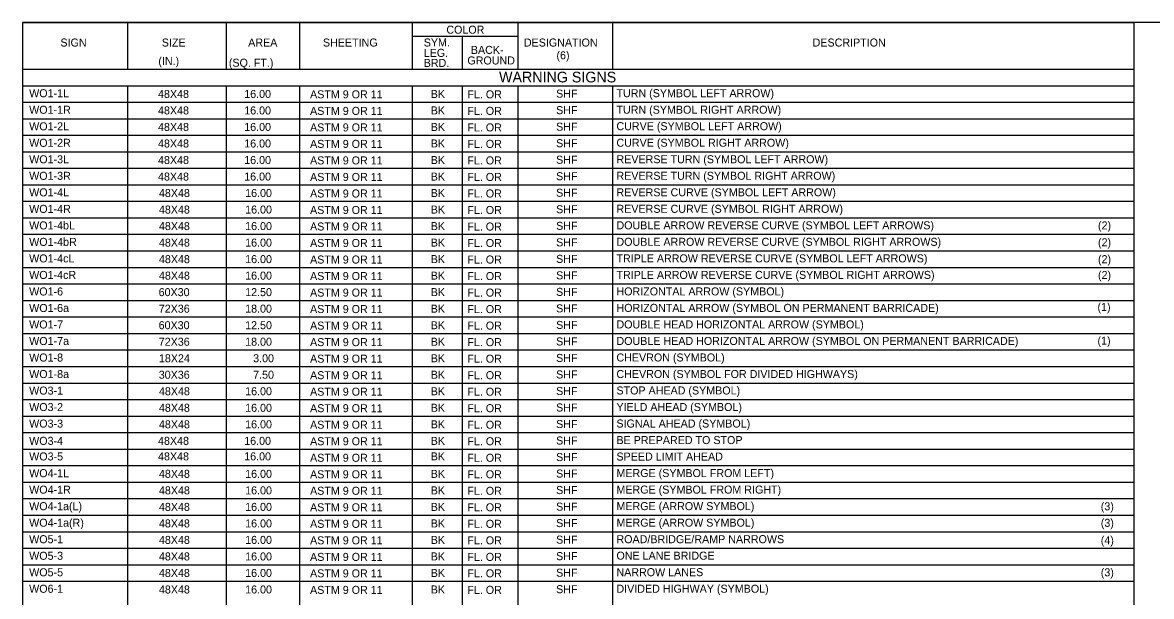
# Model space of a CAD drawing. Extents: x -439.1 to -407.9, y -458.1 to -437.7.
# Drawn here: x -439.11 to -418.9, y -447.95 to -437.68 of the extents above; entities that cross this region are included whole.
import ezdxf

# ---------------------------------------------------------------- set-up
doc = ezdxf.new("R2010")
doc.units = 0
for name, color, linetype in [('Draft_Named_Boundary', 7, 'Continuous'), ('Level 4', 7, 'Continuous'), ('Level 45', 7, 'Continuous')]:
    doc.layers.add(name, color=color, linetype=linetype)

msp = doc.modelspace()

# ---------------------------------------------------------------- linework, layer by layer
at = {"layer": 'Draft_Named_Boundary'}
msp.add_lwpolyline([(-439.109, -458.051), (-407.859, -458.051), (-407.859, -437.676), (-439.109, -437.676)], close=True, dxfattribs=at)
at = {"layer": 'Level 4'}
for p, q in [((-439.109, -437.676), (-419.212, -437.676)), ((-439.109, -437.676), (-439.109, -458.051)), ((-437.233, -437.676), (-437.233, -438.508)), ((-435.462, -437.676), (-435.462, -438.508)), ((-434.152, -437.676), (-434.152, -438.508)), ((-432.136, -437.676), (-432.136, -438.508)), ((-430.244, -437.676), (-430.244, -438.508)), ((-428.547, -437.676), (-428.547, -438.508)), ((-419.212, -437.676), (-419.212, -458.051)), ((-432.136, -437.921), (-430.244, -437.921)), ((-431.24, -437.921), (-431.24, -438.508)), ((-439.109, -438.508), (-419.212, -438.508)), ((-439.109, -438.806), (-419.212, -438.806)), ((-437.233, -438.806), (-437.233, -458.051)), ((-435.462, -438.806), (-435.462, -458.051)), ((-434.152, -438.806), (-434.152, -458.051)), ((-432.136, -438.806), (-432.136, -458.051)), ((-431.24, -438.806), (-431.24, -458.051)), ((-430.244, -438.806), (-430.244, -458.051)), ((-428.547, -438.806), (-428.547, -458.051)), ((-439.109, -439.102), (-419.212, -439.102)), ((-439.109, -439.398), (-419.212, -439.398)), ((-439.109, -439.693), (-419.212, -439.693)), ((-439.109, -439.989), (-419.212, -439.989)), ((-439.109, -440.285), (-419.212, -440.285)), ((-439.109, -440.581), (-419.212, -440.581)), ((-439.109, -440.877), (-419.212, -440.877)), ((-439.109, -441.173), (-419.212, -441.173)), ((-439.109, -441.468), (-419.212, -441.468)), ((-439.109, -441.764), (-419.212, -441.764)), ((-439.109, -442.06), (-419.212, -442.06)), ((-439.109, -442.356), (-419.212, -442.356)), ((-439.109, -442.652), (-419.212, -442.652)), ((-439.109, -442.947), (-419.212, -442.947)), ((-439.109, -443.243), (-419.212, -443.243)), ((-439.109, -443.539), (-419.212, -443.539)), ((-439.109, -443.835), (-419.212, -443.835)), ((-439.109, -444.131), (-419.212, -444.131)), ((-439.109, -444.426), (-419.212, -444.426)), ((-439.109, -444.722), (-419.212, -444.722)), ((-439.109, -445.018), (-419.212, -445.018)), ((-439.109, -445.314), (-419.212, -445.314)), ((-439.109, -445.61), (-419.212, -445.61)), ((-439.109, -445.905), (-419.212, -445.905)), ((-439.109, -446.201), (-419.212, -446.201)), ((-439.109, -446.497), (-419.212, -446.497)), ((-439.109, -446.793), (-419.212, -446.793)), ((-439.109, -447.089), (-419.212, -447.089)), ((-439.109, -447.384), (-419.212, -447.384)), ((-439.109, -447.68), (-419.212, -447.68))]:
    msp.add_line(p, q, dxfattribs=at)

# ---------------------------------------------------------------- texts
for s, height, p in [('COLOR', 0.1431, (-431.522, -437.875)), ('SIGN', 0.1433, (-438.431, -438.105)), ('SIZE', 0.1433, (-436.616, -438.105)), ('AREA', 0.1433, (-435.07, -438.105)), ('SHEETING', 0.1433, (-433.732, -438.105)), ('SYM.', 0.1433, (-431.927, -438.104)), ('LEG.', 0.1433, (-431.927, -438.29)), ('BACK-', 0.1433, (-431.083, -438.237)), ('DESIGNATION', 0.14328, (-430.134, -438.105)), ('DESCRIPTION', 0.14328, (-424.965, -438.105)), ('BRD.', 0.1433, (-431.927, -438.47)), ('GROUND', 0.1433, (-431.146, -438.426)), ('(6)', 0.1433, (-429.551, -438.333)), ('WARNING SIGNS', 0.19076, (-430.579, -438.747)), ('WO1-1L', 0.1433, (-438.991, -439.013)), ('ASTM 9 OR 11', 0.14328, (-433.962, -439.033)), ('BK', 0.1433, (-431.802, -439.026)), ('FL. OR', 0.1433, (-431.146, -439.033)), ('SHF', 0.1433, (-429.557, -439.02)), ('TURN (SYMBOL LEFT ARROW) ', 0.14328, (-428.477, -439.012)), ('WO1-1R', 0.1433, (-438.991, -439.309)), ('ASTM 9 OR 11', 0.14328, (-433.962, -439.329)), ('BK', 0.1433, (-431.802, -439.321)), ('FL. OR', 0.1433, (-431.146, -439.329)), ('SHF', 0.1433, (-429.557, -439.316)), ('TURN (SYMBOL RIGHT ARROW)', 0.14328, (-428.477, -439.308)), ('WO1-2L', 0.1433, (-438.991, -439.605)), ('ASTM 9 OR 11', 0.14328, (-433.962, -439.625)), ('BK', 0.1433, (-431.802, -439.617)), ('FL. OR', 0.1433, (-431.146, -439.625)), ('SHF', 0.1433, (-429.557, -439.612)), ('CURVE (SYMBOL LEFT ARROW) ', 0.14328, (-428.477, -439.603)), ('WO1-2R', 0.1433, (-438.991, -439.901)), ('CURVE (SYMBOL RIGHT ARROW) ', 0.14328, (-428.477, -439.899)), ('ASTM 9 OR 11', 0.14328, (-433.962, -439.92)), ('BK', 0.1433, (-431.802, -439.913)), ('FL. OR', 0.1433, (-431.146, -439.92)), ('SHF', 0.1433, (-429.557, -439.908)), ('WO1-3L', 0.1433, (-438.991, -440.196)), ('ASTM 9 OR 11', 0.14328, (-433.962, -440.216)), ('BK', 0.1433, (-431.802, -440.209)), ('FL. OR', 0.1433, (-431.146, -440.216)), ('SHF', 0.1433, (-429.557, -440.204)), ('REVERSE TURN (SYMBOL LEFT ARROW) ', 0.14328, (-428.477, -440.195)), ('WO1-3R', 0.1433, (-438.991, -440.492)), ('ASTM 9 OR 11', 0.14328, (-433.962, -440.512)), ('BK', 0.1433, (-431.802, -440.505)), ('FL. OR', 0.1433, (-431.146, -440.512)), ('SHF', 0.1433, (-429.557, -440.499)), ('REVERSE TURN (SYMBOL RIGHT ARROW) ', 0.14328, (-428.477, -440.491)), ('WO1-4L', 0.1433, (-438.991, -440.788)), ('ASTM 9 OR 11', 0.14328, (-433.962, -440.808)), ('BK', 0.1433, (-431.802, -440.8)), ('FL. OR', 0.1433, (-431.146, -440.808)), ('SHF', 0.1433, (-429.557, -440.795)), ('REVERSE CURVE (SYMBOL LEFT ARROW) ', 0.14328, (-428.477, -440.787)), ('WO1-4R', 0.1433, (-438.991, -441.084)), ('ASTM 9 OR 11', 0.14328, (-433.962, -441.104)), ('BK', 0.1433, (-431.802, -441.096)), ('FL. OR', 0.1433, (-431.146, -441.104)), ('SHF', 0.1433, (-429.557, -441.091)), ('REVERSE CURVE (SYMBOL RIGHT ARROW) ', 0.14328, (-428.477, -441.083)), ('WO1-4bL', 0.1433, (-438.991, -441.38)), ('ASTM 9 OR 11', 0.14328, (-433.962, -441.399)), ('BK', 0.1433, (-431.802, -441.392)), ('FL. OR', 0.1433, (-431.146, -441.4)), ('SHF', 0.1433, (-429.557, -441.387)), ('DOUBLE ARROW REVERSE CURVE (SYMBOL LEFT ARROWS) ', 0.14328, (-428.477, -441.378)), ('(2)', 0.1433, (-419.856, -441.38)), ('WO1-4bR', 0.1433, (-438.991, -441.675)), ('ASTM 9 OR 11', 0.14328, (-433.962, -441.695)), ('BK', 0.1433, (-431.802, -441.688)), ('FL. OR', 0.1433, (-431.146, -441.695)), ('SHF', 0.1433, (-429.557, -441.683)), ('DOUBLE ARROW REVERSE CURVE (SYMBOL RIGHT ARROWS) ', 0.14328, (-428.477, -441.674)), ('(2)', 0.1433, (-419.856, -441.682)), ('WO1-4cL', 0.1433, (-438.991, -441.971)), ('ASTM 9 OR 11', 0.14328, (-433.962, -441.991)), ('BK', 0.1433, (-431.802, -441.984)), ('FL. OR', 0.1433, (-431.146, -441.991)), ('SHF', 0.1433, (-429.557, -441.979)), ('TRIPLE ARROW REVERSE CURVE (SYMBOL LEFT ARROWS) ', 0.14328, (-428.477, -441.97)), ('(2)', 0.1433, (-419.856, -441.985)), ('WO1-4cR', 0.1433, (-438.991, -442.267)), ('ASTM 9 OR 11', 0.14328, (-433.962, -442.287)), ('BK', 0.1433, (-431.802, -442.279)), ('FL. OR', 0.1433, (-431.146, -442.287)), ('SHF', 0.1433, (-429.557, -442.274)), ('TRIPLE ARROW REVERSE CURVE (SYMBOL RIGHT ARROWS) ', 0.14328, (-428.477, -442.266)), ('(2)', 0.1433, (-419.856, -442.268)), ('WO1-6', 0.1433, (-438.991, -442.563)), ('ASTM 9 OR 11', 0.14328, (-433.962, -442.583)), ('BK', 0.1433, (-431.802, -442.575)), ('FL. OR', 0.1433, (-431.146, -442.583)), ('SHF', 0.1433, (-429.557, -442.57)), ('HORIZONTAL ARROW (SYMBOL)', 0.14328, (-428.477, -442.562)), ('WO1-6a', 0.1433, (-438.991, -442.859)), ('ASTM 9 OR 11', 0.14328, (-433.962, -442.878)), ('BK', 0.1433, (-431.802, -442.871)), ('FL. OR', 0.1433, (-431.146, -442.879)), ('SHF', 0.1433, (-429.557, -442.866)), ('HORIZONTAL ARROW (SYMBOL ON PERMANENT BARRICADE)', 0.14328, (-428.477, -442.857)), ('(1)', 0.1433, (-419.865, -442.84)), ('WO1-7', 0.1433, (-438.991, -443.154)), ('ASTM 9 OR 11', 0.14328, (-433.962, -443.174)), ('BK', 0.1433, (-431.802, -443.167)), ('FL. OR', 0.1433, (-431.146, -443.174)), ('SHF', 0.1433, (-429.557, -443.162)), ('DOUBLE HEAD HORIZONTAL ARROW (SYMBOL)', 0.14328, (-428.477, -443.153)), ('WO1-7a', 0.1433, (-438.991, -443.45)), ('ASTM 9 OR 11', 0.14328, (-433.962, -443.47)), ('BK', 0.1433, (-431.802, -443.463)), ('FL. OR', 0.1433, (-431.146, -443.47)), ('SHF', 0.1433, (-429.557, -443.458)), ('DOUBLE HEAD HORIZONTAL ARROW (SYMBOL ON PERMANENT BARRICADE)', 0.14328, (-428.477, -443.449)), ('(1)', 0.1433, (-419.865, -443.444)), ('WO1-8', 0.1433, (-438.991, -443.746)), ('CHEVRON (SYMBOL)', 0.14328, (-428.477, -443.745)), ('ASTM 9 OR 11', 0.14328, (-433.962, -443.766)), ('BK', 0.1433, (-431.802, -443.759)), ('FL. OR', 0.1433, (-431.146, -443.766)), ('SHF', 0.1433, (-429.557, -443.753)), ('WO1-8a', 0.1433, (-438.991, -444.042)), ('ASTM 9 OR 11', 0.14328, (-433.962, -444.062)), ('BK', 0.1433, (-431.802, -444.054)), ('FL. OR', 0.1433, (-431.146, -444.062)), ('SHF', 0.1433, (-429.557, -444.049)), ('CHEVRON (SYMBOL FOR DIVIDED HIGHWAYS)', 0.14328, (-428.477, -444.041)), ('WO3-1', 0.1433, (-438.991, -444.338)), ('BK', 0.1433, (-431.802, -444.35)), ('SHF', 0.1433, (-429.557, -444.345)), ('STOP AHEAD (SYMBOL) ', 0.14328, (-428.477, -444.336)), ('ASTM 9 OR 11', 0.14328, (-433.962, -444.357)), ('FL. OR', 0.1433, (-431.146, -444.358)), ('WO3-2', 0.1433, (-438.991, -444.633)), ('ASTM 9 OR 11', 0.14328, (-433.962, -444.653)), ('BK', 0.1433, (-431.802, -444.646)), ('FL. OR', 0.1433, (-431.146, -444.653)), ('SHF', 0.1433, (-429.557, -444.641)), ('YIELD AHEAD (SYMBOL) ', 0.14328, (-428.477, -444.632)), ('WO3-3 ', 0.1433, (-438.991, -444.929)), ('ASTM 9 OR 11', 0.14328, (-433.962, -444.949)), ('BK', 0.1433, (-431.802, -444.942)), ('FL. OR', 0.1433, (-431.146, -444.949)), ('SHF', 0.1433, (-429.557, -444.937)), ('SIGNAL AHEAD (SYMBOL)', 0.14328, (-428.477, -444.928)), ('WO3-4', 0.1433, (-438.991, -445.238)), ('ASTM 9 OR 11', 0.14328, (-433.962, -445.245)), ('BK', 0.1433, (-431.802, -445.238)), ('FL. OR', 0.1433, (-431.146, -445.245)), ('SHF', 0.1433, (-429.557, -445.232)), ('BE PREPARED TO STOP ', 0.14328, (-428.477, -445.224)), ('WO3-5', 0.1433, (-438.991, -445.517)), ('ASTM 9 OR 11', 0.14328, (-433.962, -445.541)), ('BK', 0.1433, (-431.802, -445.516)), ('FL. OR', 0.1433, (-431.146, -445.541)), ('SHF', 0.1433, (-429.557, -445.528)), ('SPEED LIMIT AHEAD ', 0.14328, (-428.477, -445.519)), ('WO4-1L ', 0.1433, (-438.991, -445.817)), ('ASTM 9 OR 11', 0.14328, (-433.962, -445.837)), ('BK', 0.1433, (-431.802, -445.829)), ('FL. OR', 0.1433, (-431.146, -445.837)), ('SHF', 0.1433, (-429.557, -445.824)), ('MERGE (SYMBOL FROM LEFT)', 0.14328, (-428.477, -445.815)), ('WO4-1R ', 0.1433, (-438.991, -446.112)), ('ASTM 9 OR 11', 0.14328, (-433.962, -446.132)), ('BK', 0.1433, (-431.802, -446.125)), ('FL. OR', 0.1433, (-431.146, -446.132)), ('SHF', 0.1433, (-429.557, -446.12)), ('MERGE (SYMBOL FROM RIGHT)', 0.14328, (-428.477, -446.111)), ('WO4-1a(L)', 0.1433, (-438.991, -446.408)), ('ASTM 9 OR 11', 0.14328, (-433.962, -446.428)), ('BK', 0.1433, (-431.802, -446.421)), ('FL. OR', 0.1433, (-431.146, -446.428)), ('SHF', 0.1433, (-429.557, -446.416)), ('MERGE (ARROW SYMBOL)', 0.14328, (-428.477, -446.407)), ('(3)', 0.1433, (-419.806, -446.41)), ('WO4-1a(R)', 0.1433, (-438.991, -446.704)), ('ASTM 9 OR 11', 0.14328, (-433.962, -446.724)), ('BK', 0.1433, (-431.802, -446.717)), ('FL. OR', 0.1433, (-431.146, -446.724)), ('SHF', 0.1433, (-429.557, -446.711)), ('MERGE (ARROW SYMBOL)', 0.14328, (-428.477, -446.703)), ('(3)', 0.1433, (-419.806, -446.706)), ('WO5-1 ', 0.1433, (-438.991, -447)), ('ASTM 9 OR 11', 0.14328, (-433.962, -447.02)), ('BK', 0.1433, (-431.802, -447.012)), ('FL. OR', 0.1433, (-431.146, -447.02)), ('SHF', 0.1433, (-429.557, -447.007)), ('ROAD/BRIDGE/RAMP NARROWS ', 0.14328, (-428.477, -446.999)), ('(4)', 0.1433, (-419.806, -447.018)), ('WO5-3 ', 0.1433, (-438.991, -447.296)), ('ASTM 9 OR 11', 0.14328, (-433.962, -447.316)), ('BK', 0.1433, (-431.802, -447.308)), ('FL. OR', 0.1433, (-431.146, -447.316)), ('SHF', 0.1433, (-429.557, -447.303)), ('ONE LANE BRIDGE', 0.14328, (-428.477, -447.294)), ('WO5-5', 0.1433, (-438.991, -447.592)), ('ASTM 9 OR 11', 0.14328, (-433.962, -447.611)), ('BK', 0.1433, (-431.802, -447.604)), ('FL. OR', 0.1433, (-431.146, -447.611)), ('SHF', 0.1433, (-429.557, -447.599)), ('NARROW LANES ', 0.14328, (-428.477, -447.59)), ('(3)', 0.1433, (-419.806, -447.593)), ('WO6-1 ', 0.1433, (-438.991, -447.887)), ('ASTM 9 OR 11', 0.14328, (-433.962, -447.907)), ('BK', 0.1433, (-431.802, -447.9)), ('FL. OR', 0.1433, (-431.146, -447.907)), ('SHF', 0.1433, (-429.557, -447.895)), ('DIVIDED HIGHWAY (SYMBOL)', 0.14328, (-428.477, -447.886))]:
    msp.add_text(s, height=height, dxfattribs=at).set_placement(p)
at = {"layer": 'Level 45'}
for s, p in [('(IN.)', (-436.678, -438.436)), ('(SQ. FT.)', (-435.416, -438.467)), ('48X48', (-436.684, -439.026)), ('16.00', (-435.141, -439.026)), ('48X48', (-436.684, -439.321)), ('16.00', (-435.141, -439.321)), ('48X48', (-436.684, -439.617)), ('16.00', (-435.141, -439.617)), ('48X48', (-436.684, -439.913)), ('16.00', (-435.141, -439.913)), ('48X48', (-436.684, -440.209)), ('16.00', (-435.141, -440.209)), ('48X48', (-436.684, -440.505)), ('16.00', (-435.141, -440.505)), ('48X48', (-436.668, -440.8)), ('16.00', (-435.124, -440.8)), ('48X48', (-436.668, -441.096)), ('16.00', (-435.124, -441.096)), ('48X48', (-436.668, -441.392)), ('16.00', (-435.124, -441.392)), ('48X48', (-436.668, -441.688)), ('16.00', (-435.124, -441.688)), ('48X48', (-436.668, -441.984)), ('16.00', (-435.124, -441.984)), ('48X48', (-436.668, -442.279)), ('16.00', (-435.124, -442.279)), ('60X30', (-436.673, -442.575)), ('12.50', (-435.124, -442.575)), ('72X36', (-436.671, -442.871)), ('18.00', (-435.124, -442.871)), ('60X30', (-436.673, -443.167)), ('12.50', (-435.124, -443.167)), ('72X36', (-436.671, -443.463)), ('18.00', (-435.124, -443.463)), ('18X24', (-436.668, -443.759)), ('3.00', (-434.981, -443.759)), ('30X36', (-436.671, -444.054)), ('7.50', (-434.981, -444.054)), ('48X48', (-436.668, -444.35)), ('16.00', (-435.124, -444.35)), ('48X48', (-436.668, -444.646)), ('16.00', (-435.124, -444.646)), ('48X48', (-436.668, -444.942)), ('16.00', (-435.124, -444.942)), ('48X48', (-436.684, -445.238)), ('16.00', (-435.141, -445.238)), ('48X48', (-436.684, -445.516)), ('16.00', (-435.141, -445.516)), ('48X48', (-436.668, -445.829)), ('16.00', (-435.124, -445.829)), ('48X48', (-436.668, -446.125)), ('16.00', (-435.124, -446.125)), ('48X48', (-436.668, -446.421)), ('16.00', (-435.124, -446.421)), ('48X48', (-436.668, -446.717)), ('16.00', (-435.124, -446.717)), ('48X48', (-436.668, -447.012)), ('16.00', (-435.124, -447.012)), ('48X48', (-436.668, -447.308)), ('16.00', (-435.124, -447.308)), ('48X48', (-436.668, -447.604)), ('16.00', (-435.124, -447.604)), ('48X48', (-436.668, -447.9)), ('16.00', (-435.124, -447.9))]:
    msp.add_text(s, height=0.1433, dxfattribs=at).set_placement(p)

doc.saveas('drawing.dxf')
